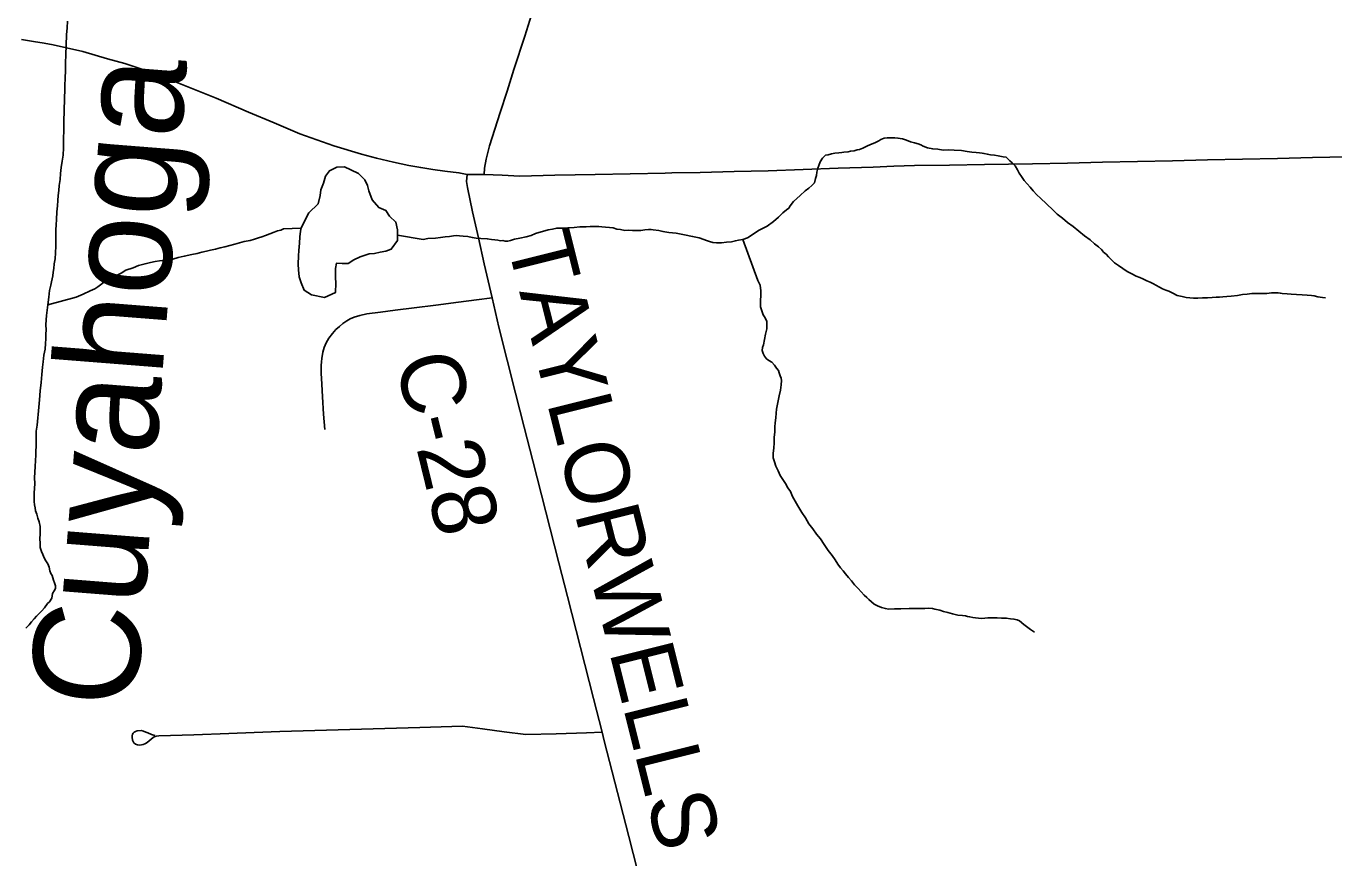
# Model space of a CAD drawing. Extents: x 103424 to 286016, y 38711 to 110967.
# Drawn here: x 154300 to 160467, y 80079 to 84001 of the extents above; entities that cross this region are included whole.
import ezdxf

# ---------------------------------------------------------------- set-up
doc = ezdxf.new("R2010")
doc.units = 0
for name, color, linetype in [('GM_X_County_Road', 7, 'Continuous'), ('GM_X_County_Road_Text', 7, 'Continuous'), ('GM_X_Minor_Lake', 7, 'Continuous'), ('GM_X_Minor_River', 7, 'Continuous'), ('GM_X_Minor_River_Text', 7, 'Continuous'), ('GM_X_Township_Road', 7, 'Continuous'), ('GM_X_US_Route', 7, 'Continuous')]:
    doc.layers.add(name, color=color, linetype=linetype)

msp = doc.modelspace()

# ---------------------------------------------------------------- linework, layer by layer
at = {"layer": 'GM_X_County_Road'}
msp.add_lwpolyline([(157183.3, 80019.5), (157142.2, 80179.3), (157101.1, 80339.2), (157063.6, 80485.2), (157026, 80631.3), (157016, 80671.2), (156975.2, 80831.1), (156934.4, 80991.1), (156893.7, 81151), (156852.9, 81311), (156812.1, 81470.9), (156771.4, 81630.9), (156730.6, 81790.8), (156689.8, 81950.8), (156649, 82110.7), (156608.3, 82270.7), (156568.6, 82426.5), (156528.9, 82582.4), (156497, 82720.1), (156460.4, 82881.1), (156432.7, 83003), (156405, 83125), (156380.6, 83240.7), (156377.3, 83269.3), (156380, 83302.2)], dxfattribs=at)
at = {"layer": 'GM_X_Minor_Lake'}
for points in [[(155789.4, 82882.5), (155792.3, 82882.3), (155818.5, 82882.4), (155844.7, 82898.7), (155874.8, 82913), (155917.1, 82927.3), (155943.3, 82929.5), (155969.5, 82935.7), (155995.7, 82939.9), (156021.8, 82950.1), (156051.9, 82990.6), (156051.7, 83041.1), (156043.5, 83077.3), (156013.1, 83105.4), (155996.9, 83131.6), (155962.6, 83145.5), (155932.2, 83181.7), (155915.9, 83224), (155909.8, 83250.2), (155897.6, 83276.3), (155867.3, 83306.4), (155830.9, 83324.4), (155800.6, 83338.4), (155764.4, 83336.1), (155730.2, 83319.8), (155712.1, 83293.5), (155702.2, 83261.1), (155690.2, 83228.8), (155686.3, 83202.5), (155676.4, 83164.1), (155632.2, 83121.5), (155596.2, 83050.7)], [(155596.2, 83050.7), (155594.2, 83034.5), (155590.3, 83008.3), (155588.4, 82978), (155586.5, 82943.7), (155584.6, 82917.5), (155582.7, 82879.1), (155584.9, 82852.9), (155587, 82818.6), (155597.2, 82790.4), (155611.4, 82756.2), (155645.8, 82734.2), (155706.3, 82722.4), (155758.6, 82744.9), (155760.5, 82789.3), (155758.3, 82815.5), (155758.2, 82857.9), (155764.1, 82884.1), (155789.4, 82882.5)]]:
    msp.add_lwpolyline(points, dxfattribs=at)
at = {"layer": 'GM_X_Minor_River'}
for points in [[(154392, 82549.2), (154393.7, 82569.4), (154393.2, 82593.6), (154394.9, 82615.9), (154396.5, 82636.1), (154398.1, 82662.4), (154401.7, 82686.7), (154403.5, 82698.9), (154405.2, 82713), (154407.1, 82723.2), (154410.5, 82755.5), (154416.1, 82779.9), (154419.9, 82796.1), (154421.7, 82810.3), (154425.4, 82824.5), (154427.2, 82840.7), (154430.9, 82858.9), (154432.5, 82881.2), (154436.1, 82903.5), (154437.6, 82931.8), (154439.1, 82964.1), (154440.5, 82994.5), (154440.1, 83018.7), (154439.7, 83040.9), (154441.3, 83065.2), (154442.9, 83089.5), (154444.2, 83125.8), (154447.8, 83154.2), (154449.4, 83178.5), (154450.9, 83202.7), (154454.5, 83227), (154456.2, 83249.3), (154459.7, 83277.6), (154461.2, 83305.9), (154464.7, 83334.3), (154470.2, 83364.7), (154473.8, 83393), (154475.2, 83427.4), (154476.4, 83473.9), (154477.8, 83508.3), (154477.2, 83538.6), (154476.7, 83564.8), (154478.3, 83591.1), (154479.8, 83619.4), (154481.4, 83643.7), (154481, 83667.9), (154482.5, 83694.2), (154482, 83724.5), (154483.5, 83752.8), (154484.7, 83795.3), (154486.1, 83829.6), (154487.5, 83864), (154489.8, 83961), (154493.3, 83993.4), (154494.7, 84025.7)], [(158113.8, 83401.7), (158131.9, 83404.1), (158146, 83406.3), (158156.1, 83406.5), (158176.2, 83408.9), (158188.3, 83411.1), (158204.4, 83413.4), (158218.4, 83417.7), (158230.5, 83420), (158246.5, 83426.3), (158264.5, 83434.7), (158282.5, 83443.1), (158302.6, 83451.6), (158320.6, 83460), (158330.6, 83466.2), (158346.6, 83472.6), (158360.7, 83474.8), (158378.8, 83475.1), (158397, 83475.5), (158411.1, 83473.7), (158421.3, 83471.9), (158433.4, 83470.1), (158451.7, 83464.3), (158470, 83456.6), (158490.2, 83450.9), (158506.4, 83447.1), (158518.7, 83441.3), (158530.9, 83435.5), (158551.2, 83427.7), (158575.5, 83422.1), (158599.8, 83420.5), (158624, 83416.9), (158650.2, 83417.4), (158676.5, 83415.8), (158710.8, 83414.4), (158737.1, 83410.9), (158759.4, 83407.2), (158779.6, 83405.6), (158795.8, 83403.8), (158807.9, 83402), (158818, 83400.2), (158832.2, 83398.4), (158848.4, 83394.7), (158866.6, 83393), (158884.8, 83389.3), (158907.1, 83385.6), (158921.2, 83383.9), (158939.7, 83366), (158950, 83356.1), (158964.4, 83342.2), (158974.8, 83324.2), (158983.1, 83308.2), (158993.5, 83292.2), (159005.9, 83274.3), (159020.3, 83258.4), (159034.8, 83242.5), (159049.2, 83224.5), (159065.7, 83206.7), (159084.1, 83190.8), (159141.6, 83135.3), (159162.1, 83115.5), (159186.7, 83095.7), (159211.3, 83075.9), (159237.9, 83056.2), (159264.5, 83034.5), (159291.1, 83012.7), (159317.7, 82993), (159338.2, 82975.2), (159356.6, 82961.4), (159371, 82947.5), (159381.3, 82935.6), (159393.5, 82925.7), (159403.9, 82913.7), (159418.2, 82899.8), (159432.6, 82886), (159451, 82872.1), (159471.4, 82858.4), (159491.9, 82844.6), (159514.3, 82832.9), (159534.6, 82823.1), (159552.9, 82815.4), (159567.1, 82809.6), (159585.5, 82799.8), (159601.7, 82794), (159616, 82786.2), (159628.2, 82780.4), (159644.5, 82770.6), (159658.8, 82762.7), (159675, 82757), (159689.3, 82751.2), (159707.6, 82741.4), (159727.9, 82731.7), (159752.3, 82726), (159770.5, 82722.3), (159788.7, 82720.6), (159804.8, 82718.9), (159825, 82719.3), (159847.2, 82719.7), (159871.4, 82720.1), (159893.6, 82722.5), (159911.7, 82722.8)], [(156051.8, 83015.1), (156171.8, 82995.2), (156193.9, 82999.6), (156230.2, 83002.3), (156254.4, 83004.8), (156276.5, 83007.2), (156296.7, 83009.6), (156314.8, 83011.9), (156328.9, 83014.2), (156343, 83012.4), (156361.2, 83010.7), (156383.4, 83009.1), (156403.7, 83005.4), (156421.9, 83001.7), (156444.1, 83000.1), (156474.4, 82998.6), (156494.7, 82994.9), (156510.9, 82993.2), (156525, 82991.4), (156537.1, 82989.6), (156547.2, 82989.8), (156559.4, 82988), (156571.5, 82988.2), (156583.5, 82990.5), (156603.6, 82996.9), (156627.7, 83001.4), (156657.9, 83008), (156682, 83014.5), (156702, 83022.9), (156762.2, 83040.1), (156782.3, 83044.5), (156802.4, 83048.9), (156826.6, 83049.4), (156854.9, 83049.9), (156885.1, 83052.4), (156911.3, 83054.9), (156941.6, 83055.5), (156959.7, 83055.8), (156971.8, 83056), (156983.9, 83056.2), (157000, 83056.5), (157014.2, 83054.7), (157032.4, 83053.1), (157050.6, 83051.4), (157068.8, 83049.7), (157085, 83043.9), (157103.2, 83042.2), (157123.5, 83038.5), (157139.6, 83038.8), (157159.8, 83037.2), (157178, 83037.5), (157198.1, 83037.8), (157218.3, 83040.2), (157234.4, 83042.5), (157246.5, 83042.7), (157256.6, 83040.9), (157282.9, 83037.3), (157303.1, 83033.7), (157331.5, 83028.1), (157365.8, 83024.7), (157404.3, 83017.3), (157442.8, 83009.9), (157473.2, 83002.4), (157495.5, 82994.7), (157507.7, 82990.9), (157521.9, 82985.1), (157538.1, 82981.3), (157556.3, 82979.6), (157578.5, 82980), (157602.7, 82982.5), (157626.9, 82984.9), (157644.9, 82989.3), (157659, 82991.6), (157679.1, 82996), (157701.2, 83002.4), (157757, 83039.8), (157795, 83058.6), (157824.9, 83079.4), (157848.8, 83100), (157868.6, 83120.6), (157886.5, 83135), (157896.4, 83143.3), (157902.3, 83153.5), (157918.1, 83174), (157934, 83188.4), (157949.9, 83202.8), (157973.7, 83225.5), (157991.6, 83237.9), (158005.5, 83250.3), (158017.4, 83262.6), (158023.1, 83282.9), (158026.9, 83297.1), (158028.6, 83313.3), (158034.3, 83331.6), (158038.1, 83343.8), (158043.9, 83362.1), (158055.7, 83378.5), (158069.5, 83392.8), (158081.6, 83395.1), (158097.7, 83399.4), (158113.8, 83401.7)], [(154401.7, 82686.7), (154536.2, 82723.5), (154568.2, 82738.2), (154602.3, 82752.9), (154624.3, 82763.4), (154638.2, 82771.8), (154650.2, 82782.1), (154664.1, 82792.4), (154684.1, 82804.9), (154748.1, 82836.3), (154770, 82850.9), (154804.1, 82861.6), (154830.2, 82872.2), (154860.3, 82880.8), (154886.4, 82887.3), (154908.5, 82891.7), (154928.6, 82894.1), (154948.8, 82896.5), (154968.9, 82898.9), (154991, 82903.3), (155017.1, 82909.9), (155045.3, 82916.4), (155081.4, 82925.2), (155105.6, 82929.6), (155127.6, 82936.1), (155149.8, 82940.5), (155169.9, 82944.9), (155192, 82949.4), (155214.1, 82955.8), (155236.2, 82960.2), (155260.3, 82966.7), (155284.4, 82973.2), (155306.4, 82979.7), (155328.5, 82986.1), (155356.7, 82990.7), (155376.8, 82997.1), (155394.8, 83003.5), (155410.9, 83007.8), (155428.9, 83014.2), (155448.9, 83022.7), (155469, 83029.1), (155485, 83035.4), (155501.1, 83039.7), (155513.1, 83046), (155595.1, 83049.3)], [(157679.1, 82996), (157751.2, 82801.3), (157761.7, 82779.3), (157764.2, 82753), (157764.6, 82728.8), (157762.9, 82710.6), (157763.2, 82694.4), (157763.5, 82678.3), (157765.7, 82668.2), (157772.1, 82650.2), (157776.3, 82640.1), (157782.5, 82630.1), (157788.8, 82620.1), (157793, 82608.1), (157793.6, 82573.8), (157786, 82549.4), (157782.4, 82523.1), (157776.8, 82498.7), (157773, 82486.5), (157771.2, 82472.4), (157775.5, 82458.3), (157781.8, 82444.3), (157792.1, 82432.3), (157802.4, 82424.4), (157816.6, 82416.6), (157829, 82402.7), (157839.3, 82388.7), (157847.6, 82376.8), (157851.8, 82366.7), (157856.1, 82352.7), (157860.4, 82340.6), (157862.6, 82330.6), (157860.9, 82310.3), (157857.3, 82284), (157851.7, 82257.6), (157838.7, 82194.8), (157837, 82176.6), (157835.4, 82154.3), (157831.8, 82130), (157830.1, 82111.8), (157830.6, 82087.6), (157827, 82061.3), (157827.4, 82037), (157825.9, 82010.7), (157822.3, 81988.4), (157822.7, 81966.2), (157829.1, 81946.1), (157835.5, 81926), (157846, 81904), (157856.5, 81882), (157868.9, 81864), (157881.3, 81844), (157891.8, 81824), (157904.2, 81806.1), (157914.7, 81784), (157927.2, 81762), (157939.7, 81740), (157958.4, 81708.1), (157975, 81682.1), (157991.7, 81654.1), (158010.3, 81630.2), (158026.9, 81606.3), (158045.4, 81584.4), (158064.1, 81556.4), (158082.7, 81528.5), (158101.3, 81504.6), (158115.8, 81484.6), (158128.3, 81464.6), (158140.7, 81446.7), (158153, 81432.8), (158163.4, 81418.8), (158177.8, 81400.9), (158192.2, 81385), (158206.7, 81367.1), (158223.1, 81349.2), (158237.5, 81333.3), (158252, 81317.4), (158264.2, 81307.5), (158274.5, 81297.6), (158299.1, 81275.8), (158315.4, 81268), (158333.7, 81260.2), (158352, 81254.5), (158366.1, 81252.7), (158394.4, 81253.2), (158424.6, 81253.8), (158465, 81254.5), (158489.2, 81254.9), (158507.3, 81255.3), (158521.4, 81255.5), (158537.6, 81255.8), (158557.7, 81256.2), (158573.9, 81254.4), (158586.1, 81252.6), (158608.4, 81247), (158626.6, 81241.2), (158646.9, 81235.6), (158669.2, 81229.9)], [(159911.7, 82722.8), (159927.9, 82723.1), (159944, 82725.4), (159962.1, 82725.8), (159982.3, 82728.1), (160012.5, 82730.7), (160036.6, 82735.2), (160058.8, 82737.6), (160080.9, 82740), (160151.5, 82741.3), (160173.7, 82743.7), (160191.8, 82744), (160203.9, 82744.2), (160214.1, 82742.4), (160224.2, 82740.6), (160246.4, 82738.9), (160266.6, 82737.3), (160290.8, 82735.7), (160317.1, 82734.1), (160341.4, 82732.6), (160361.6, 82730.9), (160373.7, 82729.1), (160391.9, 82725.4), (160402.1, 82723.5), (160414.2, 82721.7), (160428.4, 82720)], [(154297.8, 81161.6), (154313.6, 81178.1), (154325.5, 81192.4), (154337.3, 81206.8), (154349.2, 81219.1), (154361.1, 81231.5), (154373, 81243.8), (154386.9, 81258.2), (154400.6, 81278.6), (154410.6, 81286.9), (154420.4, 81303.2), (154424, 81325.5), (154431.8, 81337.8), (154437.7, 81350), (154437.5, 81362.1), (154433.2, 81376.2), (154428.9, 81388.2), (154422.5, 81410.3), (154416.2, 81420.3), (154412, 81432.4), (154407.6, 81450.5), (154401.3, 81466.5), (154393, 81480.5), (154384.7, 81494.5), (154378.3, 81510.5), (154372, 81524.6), (154365.6, 81542.6), (154365.3, 81562.8), (154364.9, 81583), (154366.5, 81607.3), (154366.2, 81623.5), (154365.9, 81641.6), (154361.4, 81663.8), (154355.1, 81681.8), (154350.7, 81700), (154344.4, 81716), (154342.1, 81730.1), (154339.8, 81744.2), (154337.5, 81760.3), (154337.2, 81776.5), (154336.8, 81800.7), (154338.4, 81820.9), (154340, 81845.2), (154339.6, 81871.5), (154341.1, 81897.7), (154342.7, 81924), (154344.2, 81952.4), (154345.7, 81978.6), (154345.4, 81998.8), (154347, 82019.1), (154346.7, 82039.3), (154346.3, 82061.5), (154347.7, 82091.8), (154351.3, 82120.1), (154359.8, 82205.1), (154363.2, 82239.6), (154366.5, 82282), (154369.9, 82320.5), (154373.2, 82358.9), (154376.6, 82393.3), (154380.2, 82417.6), (154383.7, 82450), (154389.2, 82478.4), (154390.8, 82504.7), (154392.4, 82526.9), (154392, 82549.2)], [(158669.2, 81229.9), (158693.5, 81224.3), (158715.7, 81222.6), (158729.9, 81220.9), (158740.1, 81217), (158750.2, 81215.2), (158764.3, 81213.4), (158776.5, 81211.6), (158790.6, 81209.8), (158806.8, 81208.1), (158835, 81210.6), (158857.2, 81211), (158879.4, 81211.4), (158899.6, 81209.8), (158921.8, 81210.2), (158942, 81206.5), (158958.2, 81204.8), (158974.4, 81201), (158984.6, 81197.2), (159005.1, 81179.3), (159023.5, 81165.5), (159035.8, 81155.6), (159046, 81149.8), (159056.2, 81143.9)]]:
    msp.add_lwpolyline(points, dxfattribs=at)
at = {"layer": 'GM_X_Township_Road'}
for points in [[(156459.9, 83301.7), (156462.1, 83330.9), (156470.1, 83374.6), (156484.9, 83436.9), (156535.4, 83594), (156568, 83695.4), (156600.5, 83796.7), (156650.9, 83953.9), (156699.3, 84105.1)], [(155709.2, 82099), (155702.4, 82170.8), (155697.7, 82253.4), (155693.5, 82313.6), (155691.5, 82365.5), (155690.8, 82401.7), (155692, 82418.7), (155693.5, 82433.8), (155699, 82464.6), (155705.1, 82486.4), (155714.7, 82508.3), (155727.6, 82529.5), (155744.7, 82551.9), (155759.8, 82570.5), (155777.4, 82585.3), (155793.9, 82598.5), (155812.4, 82612.1), (155827.4, 82620.4), (155847.2, 82628.5), (155873.2, 82637.4), (155906, 82644.3), (155971.7, 82652.7), (156039.8, 82661.5), (156129.5, 82673), (156232.1, 82686.2), (156339.5, 82700.1), (156424.5, 82711), (156497, 82720.1)], [(154906.8, 80655.5), (154891.1, 80661.5), (154874.4, 80668.1), (154864, 80672.6), (154852.8, 80677.1), (154842, 80679.3), (154822.7, 80678.2), (154816, 80675.6), (154809.3, 80671.5), (154804.8, 80667), (154801.8, 80662.2), (154800, 80654.8), (154799.2, 80648.4), (154800.7, 80633.9), (154804.4, 80627.6), (154808.2, 80622), (154816, 80616), (154824.5, 80611.9), (154835.7, 80611.2), (154843.1, 80611.9), (154851, 80613.8), (154859.1, 80616.8), (154865.1, 80620.5), (154878.5, 80629.4), (154890.8, 80640.2), (154896.7, 80645.1), (154904.2, 80650.3), (154912.8, 80652.9), (154925, 80654), (155090, 80659.8), (155255, 80665.7), (155375.5, 80670), (155496, 80674.3), (155661, 80679.3), (155826, 80684.3), (155991, 80689.3), (156156, 80694.3), (156256.6, 80697.4), (156357.2, 80700.5), (156452.1, 80687.7), (156554.3, 80674), (156656.5, 80660.2), (156799.6, 80664.6), (156942.7, 80668.9), (157016, 80671.2)]]:
    msp.add_lwpolyline(points, dxfattribs=at)
at = {"layer": 'GM_X_US_Route'}
for points in [[(154277.7, 83937.9), (154334, 83929.3), (154384.1, 83921.2), (154426.7, 83912.6), (154490.4, 83898.5), (154567, 83881.3), (154684.1, 83847.8), (154764.5, 83825.7), (154896.7, 83781.4), (155046.7, 83721.3), (155196.7, 83661.1), (155348.5, 83596.3), (155469.3, 83544.8), (155590, 83493.3), (155670.5, 83465.5), (155750.9, 83437.7), (155882, 83397.2), (155952.7, 83379.4), (156032.5, 83360), (156104.8, 83344.9), (156160.9, 83334.6), (156217.1, 83326), (156273.7, 83317.9), (156340.6, 83310.4), (156380, 83302.2), (156459.9, 83301.7), (156544.3, 83298.2), (156628.8, 83294.7), (156793.8, 83297.9), (156888.3, 83299.6), (156982.9, 83301.4), (157147.9, 83304.9), (157312.9, 83308.5), (157344.9, 83309.2)], [(154277.7, 83937.9), (154334, 83929.3), (154384.1, 83921.2), (154426.7, 83912.6), (154490.4, 83898.5), (154567, 83881.3), (154684.1, 83847.8), (154764.5, 83825.7), (154896.7, 83781.4), (155046.7, 83721.3), (155196.7, 83661.1), (155348.5, 83596.3), (155469.3, 83544.8), (155590, 83493.3), (155670.5, 83465.5), (155750.9, 83437.7), (155882, 83397.2), (155952.7, 83379.4), (156032.5, 83360), (156104.8, 83344.9), (156160.9, 83334.6), (156217.1, 83326), (156273.7, 83317.9), (156340.6, 83310.4), (156380, 83302.2), (156459.9, 83301.7), (156544.3, 83298.2), (156628.8, 83294.7), (156793.8, 83297.9), (156888.3, 83299.6), (156982.9, 83301.4), (157147.9, 83304.9), (157312.9, 83308.5), (157344.9, 83309.2)], [(157344.9, 83309.2), (157478, 83312), (157638.9, 83315.4), (157799.7, 83318.9), (157964.7, 83325), (158129.7, 83331), (158294.6, 83337.1), (158392.3, 83340.7), (158490, 83344.3), (158655, 83346.6), (158820.1, 83348.9), (158932.8, 83350.5), (159045.6, 83352), (159210.6, 83355.7), (159375.6, 83359.4), (159540.7, 83363.1), (159705.7, 83366.8), (159870.7, 83370.5), (160035.7, 83374.2), (160200.8, 83377.9), (160365.8, 83381.6), (160530.8, 83385.3)], [(157344.9, 83309.2), (157478, 83312), (157638.9, 83315.4), (157799.7, 83318.9), (157964.7, 83325), (158129.7, 83331), (158294.6, 83337.1), (158392.3, 83340.7), (158490, 83344.3), (158655, 83346.6), (158820.1, 83348.9), (158932.8, 83350.5), (159045.6, 83352), (159210.6, 83355.7), (159375.6, 83359.4), (159540.7, 83363.1), (159705.7, 83366.8), (159870.7, 83370.5), (160035.7, 83374.2), (160200.8, 83377.9), (160365.8, 83381.6), (160530.8, 83385.3)]]:
    msp.add_lwpolyline(points, dxfattribs=at)

# ---------------------------------------------------------------- texts
at = {"layer": 'GM_X_County_Road_Text'}
for s, height, rotation, p in [('TAYLORWELLS', 301.872, 284.03796, (156564.6, 82989.5)), ('C-28', 301.87, 283.77894, (156037.9, 82427.5))]:
    msp.add_text(s, height=height, rotation=rotation, dxfattribs=at).set_placement(p)
at = {"layer": 'GM_X_Minor_River_Text'}
msp.add_text('Cuyahoga', height=503.47, rotation=85.49315, dxfattribs=at).set_placement((154817.5, 80777.4))

doc.saveas('drawing.dxf')
